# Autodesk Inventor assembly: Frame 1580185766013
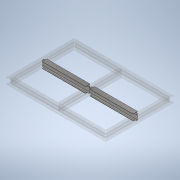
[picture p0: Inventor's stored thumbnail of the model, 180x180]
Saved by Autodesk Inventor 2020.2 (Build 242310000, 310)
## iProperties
Created: 2020-01
Part Number: Frame 1580185766013
Document SubType Name: Assembly
Designer: thira
_FrameDoc: Frame Assembly
_Version: 15.0.0
Author: thira
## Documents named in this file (8)
- F:\99.โปรแกรมอัดหน้าจอ\Synergysoft\FRAME\Frame_Generator\Frame\Frame 1580185766013.iam
- F:\99.โปรแกรมอัดหน้าจอ\Synergysoft\FRAME\Frame_Generator\Frame\Skeleton 1580185766014.ipt
- F:\99.โปรแกรมอัดหน้าจอ\Synergysoft\FRAME\Frame_Generator\Frame\ANSI M3 x 2.9 1580185967747.ipt
- F:\99.โปรแกรมอัดหน้าจอ\Synergysoft\FRAME\Frame_Generator\Frame\ANSI M3 x 2.9 1580185991661.ipt
- F:\99.โปรแกรมอัดหน้าจอ\Synergysoft\FRAME\Frame_Generator\Frame\ANSI M3 x 2.9 1580185919414.ipt
- F:\99.โปรแกรมอัดหน้าจอ\Synergysoft\FRAME\Frame_Generator\Frame\ANSI M3 x 2.9 1580185919415.ipt
- F:\99.โปรแกรมอัดหน้าจอ\Synergysoft\FRAME\Frame_Generator\Frame\ANSI M3 x 2.9 1580185919416.ipt
- F:\99.โปรแกรมอัดหน้าจอ\Synergysoft\FRAME\Frame_Generator\Frame\ANSI M3 x 2.9 1580185919417.ipt
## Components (7 placed, 2 different names)
1. Frame Reference Model
2. ANSI M3 x 2.9:1
3. ANSI M3 x 2.9:2
4. ANSI M3 x 2.9:1
5. ANSI M3 x 2.9:2
6. ANSI M3 x 2.9:3
7. ANSI M3 x 2.9:4
